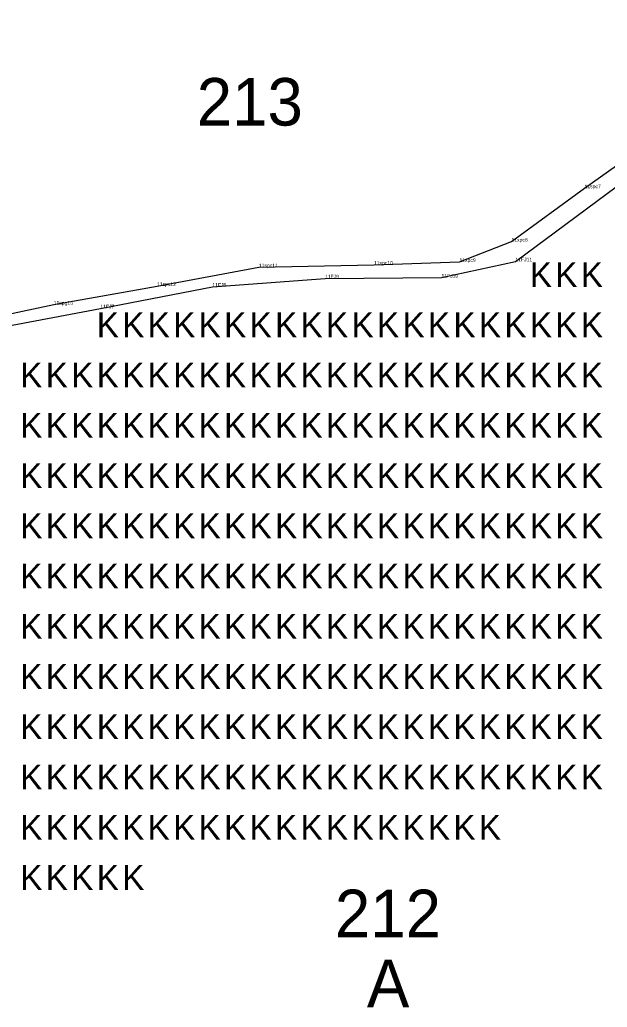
# Model space of a CAD drawing. Extents: x 2072529 to 2268812, y 436423 to 470008.
# Drawn here: x 2231127 to 2231934, y 446771 to 448127 of the extents above; entities that cross this region are included whole.
import ezdxf

# ---------------------------------------------------------------- set-up
doc = ezdxf.new("R2010")
doc.units = 0
for name, color, linetype in [('Old_Level_10', 7, 'Continuous'), ('Old_Level_20', 7, 'Continuous'), ('Old_Level_52', 7, 'Continuous'), ('Old_Level_55', 7, 'Continuous'), ('Old_Level_60', 7, 'Continuous'), ('Old_Level_62', 7, 'Continuous')]:
    doc.layers.add(name, color=color, linetype=linetype)

msp = doc.modelspace()

# ---------------------------------------------------------------- linework, layer by layer
at = {"layer": 'Old_Level_10'}
msp.add_lwpolyline([(2230769.394, 447951.882), (2230820.468, 447870.14), (2230875.802, 447771.916), (2230917.643, 447710.638), (2230955.8, 447692.492), (2231037.496, 447706.907), (2231173.407, 447735.498), (2231315.304, 447761.122), (2231455.152, 447786.77), (2231613.245, 447790.272), (2231730.779, 447794.105), (2231802.313, 447822.04), (2231902.637, 447895.433), (2231968.706, 447942.06), (2232060.909, 448002.163), (2232107.899, 448039.336), (2232157.408, 448074.653), (2232140.017, 448092.714), (2232118.49, 448126.789)], dxfattribs=at)
at = {"layer": 'Old_Level_20'}
for p, q in [((2231902.637, 447895.433), (2231902.637, 447895.433)), ((2231802.313, 447822.04), (2231802.313, 447822.04)), ((2231807.646, 447794.925), (2231807.646, 447794.925)), ((2231455.152, 447786.77), (2231455.152, 447786.77)), ((2231613.245, 447790.272), (2231613.245, 447790.272)), ((2231730.779, 447794.105), (2231730.779, 447794.105)), ((2231546.1, 447771.484), (2231546.1, 447771.484)), ((2231706.131, 447772.616), (2231706.131, 447772.616)), ((2231315.304, 447761.122), (2231315.304, 447761.122)), ((2231391.369, 447760.081), (2231391.369, 447760.081)), ((2231173.407, 447735.498), (2231173.407, 447735.498)), ((2231173.407, 447735.498), (2231173.407, 447735.498)), ((2231237.511, 447730.295), (2231237.511, 447730.295))]:
    msp.add_line(p, q, dxfattribs=at)
at = {"layer": 'Old_Level_52'}
msp.add_lwpolyline([(2230759.811, 447936.011), (2230828.534, 447831.652), (2230863.533, 447765.149), (2230929.3, 447679.936), (2230960.246, 447676.326), (2231099.106, 447704.027), (2231237.511, 447730.295), (2231391.369, 447760.081), (2231546.1, 447771.484), (2231706.131, 447772.616), (2231807.646, 447794.925), (2231974.226, 447918.42)], dxfattribs=at)

# ---------------------------------------------------------------- texts
at = {"layer": 'Old_Level_55'}
for p in [(2231827.479, 447759.791), (2231862.479, 447759.791), (2231897.479, 447759.791), (2231232.479, 447690.791), (2231267.479, 447690.791), (2231302.479, 447690.791), (2231337.479, 447690.791), (2231372.479, 447690.791), (2231407.479, 447690.791), (2231442.479, 447690.791), (2231477.479, 447690.791), (2231512.479, 447690.791), (2231547.479, 447690.791), (2231582.479, 447690.791), (2231617.479, 447690.791), (2231652.479, 447690.791), (2231687.479, 447690.791), (2231722.479, 447690.791), (2231757.479, 447690.791), (2231792.479, 447690.791), (2231827.479, 447690.791), (2231862.479, 447690.791), (2231897.479, 447690.791), (2231127.479, 447621.791), (2231162.479, 447621.791), (2231197.479, 447621.791), (2231232.479, 447621.791), (2231267.479, 447621.791), (2231302.479, 447621.791), (2231337.479, 447621.791), (2231372.479, 447621.791), (2231407.479, 447621.791), (2231442.479, 447621.791), (2231477.479, 447621.791), (2231512.479, 447621.791), (2231547.479, 447621.791), (2231582.479, 447621.791), (2231617.479, 447621.791), (2231652.479, 447621.791), (2231687.479, 447621.791), (2231722.479, 447621.791), (2231757.479, 447621.791), (2231792.479, 447621.791), (2231827.479, 447621.791), (2231862.479, 447621.791), (2231897.479, 447621.791), (2231127.479, 447552.791), (2231162.479, 447552.791), (2231197.479, 447552.791), (2231232.479, 447552.791), (2231267.479, 447552.791), (2231302.479, 447552.791), (2231337.479, 447552.791), (2231372.479, 447552.791), (2231407.479, 447552.791), (2231442.479, 447552.791), (2231477.479, 447552.791), (2231512.479, 447552.791), (2231547.479, 447552.791), (2231582.479, 447552.791), (2231617.479, 447552.791), (2231652.479, 447552.791), (2231687.479, 447552.791), (2231722.479, 447552.791), (2231757.479, 447552.791), (2231792.479, 447552.791), (2231827.479, 447552.791), (2231862.479, 447552.791), (2231897.479, 447552.791), (2231127.479, 447483.791), (2231162.479, 447483.791), (2231197.479, 447483.791), (2231232.479, 447483.791), (2231267.479, 447483.791), (2231302.479, 447483.791), (2231337.479, 447483.791), (2231372.479, 447483.791), (2231407.479, 447483.791), (2231442.479, 447483.791), (2231477.479, 447483.791), (2231512.479, 447483.791), (2231547.479, 447483.791), (2231582.479, 447483.791), (2231617.479, 447483.791), (2231652.479, 447483.791), (2231687.479, 447483.791), (2231722.479, 447483.791), (2231757.479, 447483.791), (2231792.479, 447483.791), (2231827.479, 447483.791), (2231862.479, 447483.791), (2231897.479, 447483.791), (2231127.479, 447414.791), (2231162.479, 447414.791), (2231197.479, 447414.791), (2231232.479, 447414.791), (2231267.479, 447414.791), (2231302.479, 447414.791), (2231337.479, 447414.791), (2231372.479, 447414.791), (2231407.479, 447414.791), (2231442.479, 447414.791), (2231477.479, 447414.791), (2231512.479, 447414.791), (2231547.479, 447414.791), (2231582.479, 447414.791), (2231617.479, 447414.791), (2231652.479, 447414.791), (2231687.479, 447414.791), (2231722.479, 447414.791), (2231757.479, 447414.791), (2231792.479, 447414.791), (2231827.479, 447414.791), (2231862.479, 447414.791), (2231897.479, 447414.791), (2231127.479, 447345.791), (2231162.479, 447345.791), (2231197.479, 447345.791), (2231232.479, 447345.791), (2231267.479, 447345.791), (2231302.479, 447345.791), (2231337.479, 447345.791), (2231372.479, 447345.791), (2231407.479, 447345.791), (2231442.479, 447345.791), (2231477.479, 447345.791), (2231512.479, 447345.791), (2231547.479, 447345.791), (2231582.479, 447345.791), (2231617.479, 447345.791), (2231652.479, 447345.791), (2231687.479, 447345.791), (2231722.479, 447345.791), (2231757.479, 447345.791), (2231792.479, 447345.791), (2231827.479, 447345.791), (2231862.479, 447345.791), (2231897.479, 447345.791), (2231127.479, 447276.791), (2231162.479, 447276.791), (2231197.479, 447276.791), (2231232.479, 447276.791), (2231267.479, 447276.791), (2231302.479, 447276.791), (2231337.479, 447276.791), (2231372.479, 447276.791), (2231407.479, 447276.791), (2231442.479, 447276.791), (2231477.479, 447276.791), (2231512.479, 447276.791), (2231547.479, 447276.791), (2231582.479, 447276.791), (2231617.479, 447276.791), (2231652.479, 447276.791), (2231687.479, 447276.791), (2231722.479, 447276.791), (2231757.479, 447276.791), (2231792.479, 447276.791), (2231827.479, 447276.791), (2231862.479, 447276.791), (2231897.479, 447276.791), (2231127.479, 447207.791), (2231162.479, 447207.791), (2231197.479, 447207.791), (2231232.479, 447207.791), (2231267.479, 447207.791), (2231302.479, 447207.791), (2231337.479, 447207.791), (2231372.479, 447207.791), (2231407.479, 447207.791), (2231442.479, 447207.791), (2231477.479, 447207.791), (2231512.479, 447207.791), (2231547.479, 447207.791), (2231582.479, 447207.791), (2231617.479, 447207.791), (2231652.479, 447207.791), (2231687.479, 447207.791), (2231722.479, 447207.791), (2231757.479, 447207.791), (2231792.479, 447207.791), (2231827.479, 447207.791), (2231862.479, 447207.791), (2231897.479, 447207.791), (2231127.479, 447138.791), (2231162.479, 447138.791), (2231197.479, 447138.791), (2231232.479, 447138.791), (2231267.479, 447138.791), (2231302.479, 447138.791), (2231337.479, 447138.791), (2231372.479, 447138.791), (2231407.479, 447138.791), (2231442.479, 447138.791), (2231477.479, 447138.791), (2231512.479, 447138.791), (2231547.479, 447138.791), (2231582.479, 447138.791), (2231617.479, 447138.791), (2231652.479, 447138.791), (2231687.479, 447138.791), (2231722.479, 447138.791), (2231757.479, 447138.791), (2231792.479, 447138.791), (2231827.479, 447138.791), (2231862.479, 447138.791), (2231897.479, 447138.791), (2231127.479, 447069.791), (2231162.479, 447069.791), (2231197.479, 447069.791), (2231232.479, 447069.791), (2231267.479, 447069.791), (2231302.479, 447069.791), (2231337.479, 447069.791), (2231372.479, 447069.791), (2231407.479, 447069.791), (2231442.479, 447069.791), (2231477.479, 447069.791), (2231512.479, 447069.791), (2231547.479, 447069.791), (2231582.479, 447069.791), (2231617.479, 447069.791), (2231652.479, 447069.791), (2231687.479, 447069.791), (2231722.479, 447069.791), (2231757.479, 447069.791), (2231792.479, 447069.791), (2231827.479, 447069.791), (2231862.479, 447069.791), (2231897.479, 447069.791), (2231127.479, 447000.791), (2231162.479, 447000.791), (2231197.479, 447000.791), (2231232.479, 447000.791), (2231267.479, 447000.791), (2231302.479, 447000.791), (2231337.479, 447000.791), (2231372.479, 447000.791), (2231407.479, 447000.791), (2231442.479, 447000.791), (2231477.479, 447000.791), (2231512.479, 447000.791), (2231547.479, 447000.791), (2231582.479, 447000.791), (2231617.479, 447000.791), (2231652.479, 447000.791), (2231687.479, 447000.791), (2231722.479, 447000.791), (2231757.479, 447000.791), (2231127.479, 446931.791), (2231162.479, 446931.791), (2231197.479, 446931.791), (2231232.479, 446931.791), (2231267.479, 446931.791)]:
    msp.add_text('K', height=34, dxfattribs=at).set_placement(p)
at = {"layer": 'Old_Level_60'}
for s, p in [('11spc7', (2231902.637, 447895.433)), ('11xpc8', (2231802.313, 447822.04)), ('11spc10', (2231613.245, 447790.272)), ('11xpc9', (2231730.779, 447794.105)), ('11FJ11', (2231807.646, 447794.925)), ('11spc11', (2231455.152, 447786.77)), ('11FJ9', (2231546.1, 447771.484)), ('11FJ10', (2231706.131, 447772.616)), ('11spc12', (2231315.304, 447761.122)), ('11FJ8', (2231391.369, 447760.081)), ('11spg13', (2231173.407, 447735.498)), ('11spg13', (2231173.407, 447735.498)), ('11FJ7', (2231237.511, 447730.295))]:
    msp.add_text(s, height=5, dxfattribs=at).set_placement(p)
at = {"layer": 'Old_Level_62'}
for s, p in [('213', (2231369.877, 447981.425)), ('212', (2231559.667, 446866.713)), ('A', (2231603.62, 446770.576))]:
    msp.add_text(s, height=65.34, dxfattribs=at).set_placement(p)

doc.saveas('drawing.dxf')
